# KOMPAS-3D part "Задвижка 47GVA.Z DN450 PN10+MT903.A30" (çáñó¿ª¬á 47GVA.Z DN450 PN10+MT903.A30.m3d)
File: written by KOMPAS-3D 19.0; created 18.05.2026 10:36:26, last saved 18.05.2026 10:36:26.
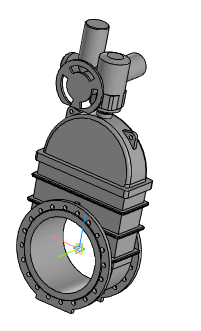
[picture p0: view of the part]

Document properties: Автор: Энергия; Полное имя файла: ..\Задвижка 47GVA.Z DN350_DN1200+MT903.A\Задвижка 47GVA.Z DN450 PN10+MT903.A30.a3d

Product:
- Part/product: Задвижка 47GVA.Z DN450 PN10+MT903.A30
    Масса: 924.592
  - Body: Электропривод МТ903.А30 без блока управления
      Масса: 163.268
  - Body: Задвижка 47GVA.Z DN450 PN10 без исполнит. мех.
      Масса: 761.324

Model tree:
1. Операция без истории:1
2. Операция без истории:2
